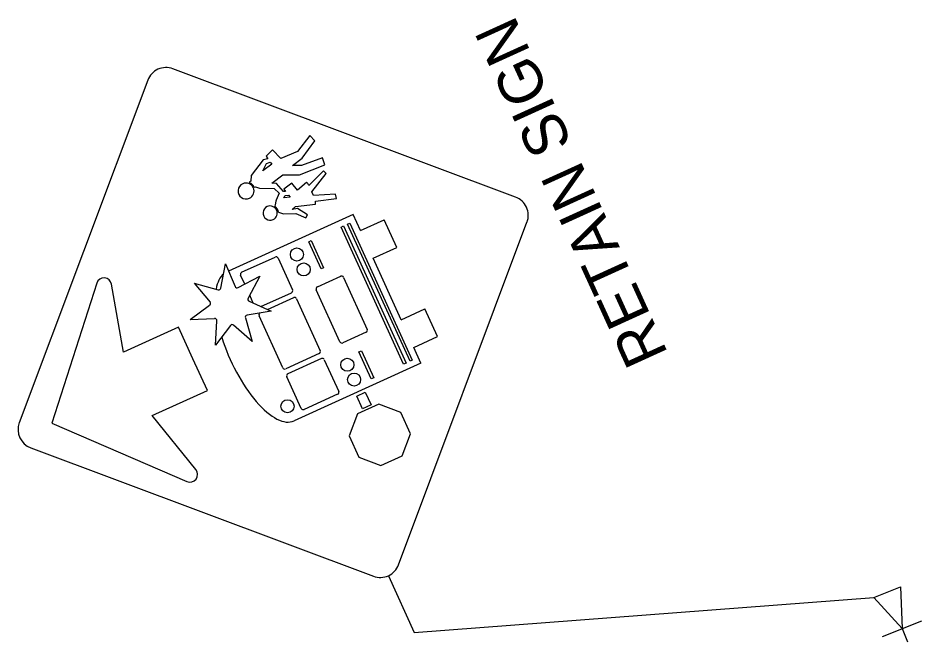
# Model space of a CAD drawing. Extents: x 2096999 to 2102576, y 682920 to 687015.
# Drawn here: x 2101971.4 to 2102115.9, y 683833.4 to 683933.2 of the extents above; entities that cross this region are included whole.
import ezdxf

# ---------------------------------------------------------------- set-up
doc = ezdxf.new("R2010")
doc.units = 0
doc.layers.add('Default', color=7, linetype='Continuous')

msp = doc.modelspace()

# ---------------------------------------------------------------- linework, layer by layer
at = {"layer": 'Default'}
for p, q in [((2102013.89, 683904.46), (2102013.89, 683904.46)), ((2102014.09, 683904.83), (2102014.09, 683904.83)), ((2102014.64, 683904.87), (2102014.64, 683904.87)), ((2102014.88, 683904.57), (2102014.88, 683904.57)), ((2102012.5, 683903.34), (2102012.5, 683903.34)), ((2102012.57, 683903.91), (2102012.57, 683903.91)), ((2102024.99, 683901.77), (2102005.05, 683892.7)), ((2102013.83, 683901.9), (2102013.83, 683901.9)), ((2102015.79, 683901.98), (2102015.79, 683901.98)), ((2102017.65, 683901.74), (2102017.65, 683901.74)), ((2102026.14, 683899.23), (2102024.99, 683901.77)), ((2102017.42, 683901.28), (2102017.42, 683901.28)), ((2102026.14, 683899.23), (2102029.94, 683900.96)), ((2102031.96, 683896.52), (2102029.94, 683900.96)), ((2102028.16, 683894.79), (2102031.96, 683896.52)), ((2102007.13, 683892.55), (2102012.5, 683894.99)), ((2102012.96, 683894.82), (2102015.27, 683889.74)), ((2102032.63, 683884.96), (2102028.16, 683894.79)), ((2102003.82, 683890.03), (2102004.56, 683893.9)), ((2102004.56, 683893.9), (2102006.08, 683890.26)), ((2102006.57, 683890.09), (2102010.05, 683891.92)), ((2102007.62, 683890.64), (2102006.96, 683892.09)), ((2102010.05, 683891.92), (2102008.15, 683888.39)), ((2101984.07, 683891.16), (2101984.07, 683891.16)), ((2101999.52, 683890.81), (2102002.07, 683887.76)), ((2101999.52, 683890.81), (2102003.39, 683889.76)), ((2102008.99, 683887.62), (2102008.42, 683888.88)), ((2102010.2, 683887.06), (2102015.09, 683889.28)), ((2102011.26, 683886.58), (2102015.45, 683888.49)), ((2101998.87, 683884.98), (2102002.01, 683887.26)), ((2102008.32, 683887.91), (2102011.86, 683886.31)), ((2102015.91, 683888.32), (2102019.7, 683879.99)), ((2102011.86, 683886.31), (2102008, 683885.68)), ((2102013.7, 683877.26), (2102009.92, 683885.59)), ((2102032.63, 683884.96), (2102036.43, 683886.69)), ((2102038.45, 683882.25), (2102036.43, 683886.69)), ((2101998.87, 683884.98), (2102002.8, 683885.16)), ((2102002.97, 683880.86), (2102003.17, 683884.8)), ((2102005.32, 683884.03), (2102002.97, 683880.86)), ((2102008.79, 683881.47), (2102005.83, 683884.08)), ((2102007.73, 683885.24), (2102008.79, 683881.47)), ((2102034.65, 683880.52), (2102038.45, 683882.25)), ((2102035.8, 683877.99), (2102034.65, 683880.52)), ((2102019.53, 683879.53), (2102014.17, 683877.09)), ((2102019.89, 683878.73), (2102014.53, 683876.3)), ((2102020.35, 683878.56), (2102022.66, 683873.49)), ((2102035.8, 683877.99), (2102015.51, 683868.76)), ((2102016.66, 683870.76), (2102014.35, 683875.83)), ((2102022.48, 683873.03), (2102017.12, 683870.59)), ((2102029.06, 683871.43), (2102025.64, 683869.88)), ((2102032.58, 683870.11), (2102029.06, 683871.43)), ((2102025.64, 683869.88), (2102024.33, 683866.36)), ((2102034.13, 683866.7), (2102032.58, 683870.11)), ((2102032.82, 683863.18), (2102034.13, 683866.7)), ((2102024.33, 683866.36), (2102025.88, 683862.94)), ((2102025.88, 683862.94), (2102029.4, 683861.63)), ((2102029.4, 683861.63), (2102032.82, 683863.18)), ((2102108.25, 683840.5), (2102112.5, 683842.19)), ((2102112.5, 683842.19), (2102112.81, 683835.54)), ((2102112.81, 683835.54), (2102108.25, 683840.5)), ((2102109.62, 683834.28), (2102115.95, 683836.79)), ((2102112.81, 683835.54), (2102113.66, 683833.39))]:
    msp.add_line(p, q, dxfattribs=at)
for points in [[(2102050.94, 683904.58), (2101996.14, 683925.12)], [(2101992.1, 683923.28), (2101971.56, 683868.48)], [(2102013.02, 683902.17), (2102013.83, 683901.9), (2102015.79, 683901.98), (2102017.42, 683901.28), (2102017.65, 683901.74), (2102016.05, 683902.76), (2102015.23, 683902.62), (2102015.72, 683903.09), (2102018.94, 683903.45), (2102018.92, 683903.92), (2102022.32, 683904.35), (2102022.14, 683905.05), (2102018.61, 683904.82), (2102018.35, 683905.43), (2102020.66, 683908.36), (2102020.24, 683908.79), (2102017.89, 683906.43), (2102017.83, 683906.54), (2102017.78, 683906.65), (2102017.69, 683906.78), (2102017.6, 683906.86), (2102017.51, 683906.91), (2102016.08, 683905.7), (2102015.16, 683906.8), (2102013.9, 683905.86), (2102014.15, 683905.5), (2102013.8, 683905.48), (2102012.68, 683906.73), (2102011.95, 683906.82), (2102013.72, 683908.13), (2102016.36, 683908.12), (2102020.42, 683909.75), (2102020.08, 683910.88), (2102016.69, 683909.62), (2102015.26, 683909.64), (2102016.81, 683910.81), (2102018.83, 683913.61), (2102018.02, 683914.44), (2102016.08, 683911.86), (2102013.37, 683910.78), (2102012.04, 683912.17), (2102011.06, 683911.13), (2102011.33, 683910.69), (2102010.56, 683910.56), (2102008.63, 683908.01), (2102008.61, 683907.14), (2102008.39, 683907), (2102008.4, 683906.88)], [(2102011.69, 683910.18), (2102011.96, 683909.84), (2102010.54, 683908.76), (2102011.13, 683909.97), (2102011.69, 683910.18)], [(2102009.15, 683906.16), (2102009.33, 683906.24), (2102009.98, 683905.99), (2102010.04, 683906), (2102012.32, 683905.93), (2102013.15, 683905.2), (2102012.63, 683904.09), (2102012.57, 683903.91), (2102012.5, 683903.34)], [(2102014.64, 683904.87), (2102014.88, 683904.57), (2102013.89, 683904.46), (2102014.09, 683904.83), (2102014.64, 683904.87)], [(2102012.5, 683903.34), (2102012.45, 683903.11)], [(2102032.24, 683845.75), (2102052.77, 683900.55)], [(2102019.24, 683890.21), (2102022.97, 683891.91)], [(2102023.43, 683891.73), (2102027.21, 683883.41)], [(2101983.95, 683890.81), (2101976.74, 683868.38), (2101998.38, 683859.08)], [(2101999.33, 683878.7), (2101997.02, 683883.77), (2101988.23, 683879.77), (2101986.32, 683890.65)], [(2102022.85, 683881.42), (2102019.07, 683889.75)], [(2102027.04, 683882.94), (2102023.31, 683881.25)], [(2101999.81, 683860.97), (2101992.83, 683869.62), (2102001.64, 683873.63), (2101999.33, 683878.7)], [(2101973.4, 683864.45), (2102028.2, 683843.91)], [(2102030.6, 683843.99), (2102034.73, 683834.91), (2102108.25, 683840.5)]]:
    msp.add_lwpolyline(points, dxfattribs=at)
for points in [[(2102033.04, 683877.84), (2102023.06, 683899.79), (2102023.44, 683899.96), (2102033.42, 683878.01)], [(2102034.06, 683878.3), (2102024.07, 683900.25), (2102024.45, 683900.42), (2102034.43, 683878.47)], [(2102019.86, 683893.11), (2102017.89, 683897.43), (2102018.27, 683897.61), (2102020.24, 683893.28)], [(2102027.87, 683875.49), (2102025.9, 683879.81), (2102026.28, 683879.99), (2102028.25, 683875.66)], [(2102026.9, 683873.35), (2102027.82, 683871.33), (2102026.47, 683870.72), (2102025.55, 683872.73)]]:
    msp.add_lwpolyline(points, close=True, dxfattribs=at)
for centre in [(2102015.97, 683895.39), (2102017.05, 683893.01), (2102024.03, 683877.75), (2102025.11, 683875.37), (2102014.47, 683871.11)]:
    msp.add_circle(centre, 1.05, dxfattribs=at)
for centre, radius, start, end in [((2101995.04, 683922.18), 3.14, 69.4559, 159.458), ((2102007.84, 683905.55), 1.28, 114.458, 294.458), ((2102007.84, 683905.55), 1.28, 294.458, 114.458), ((2102007.84, 683905.55), 1.44, 25.2657, 67.1381), ((2102049.84, 683901.65), 3.14, 339.4559, 69.458), ((2102011.69, 683902.02), 1.14, 114.458, 294.458), ((2102011.69, 683902.02), 1.14, 294.458, 114.458), ((2102011.69, 683902.02), 1.33, 6.57, 55.3516), ((2102012.64, 683894.67), 0.348, 24.458, 114.458), ((2101985.11, 683890.44), 1.22, 9.9853, 162.16), ((2102007.28, 683892.23), 0.348, 114.458, 204.458), ((2102023.11, 683891.59), 0.348, 24.458, 114.458), ((2102003.48, 683890.09), 0.348, 254.7728, 349.1199), ((2102006.4, 683890.4), 0.348, 202.6931, 297.6908), ((2102019.38, 683889.89), 0.348, 114.458, 204.458), ((2102008.46, 683888.23), 0.348, 151.6716, 245.6888), ((2102014.95, 683889.6), 0.348, 294.458, 24.458), ((2102015.6, 683888.17), 0.348, 24.458, 114.458), ((2102001.81, 683887.54), 0.348, 305.9926, 39.9359), ((2102008.06, 683885.33), 0.348, 99.3189, 195.734), ((2102010.23, 683885.73), 0.348, 138.9148, 204.458), ((2102002.82, 683884.82), 0.348, 357.0816, 92.756), ((2102005.6, 683883.82), 0.348, 48.5085, 143.3177), ((2102026.9, 683883.26), 0.348, 294.458, 24.458), ((2102023.17, 683881.57), 0.348, 204.458, 294.458), ((2102019.38, 683879.84), 0.348, 294.458, 24.458), ((2102020.03, 683878.42), 0.348, 24.458, 114.458), ((2102014.02, 683877.41), 0.348, 204.458, 294.458), ((2102014.67, 683875.98), 0.348, 114.458, 204.458), ((2102022.34, 683873.34), 0.348, 294.458, 24.458), ((2102016.98, 683870.91), 0.348, 204.458, 294.458), ((2101974.5, 683867.38), 3.14, 159.458, 249.458), ((2101998.86, 683860.2), 1.22, 246.7557, 38.9307), ((2102029.3, 683846.85), 3.14, 249.458, 339.458)]:
    msp.add_arc(centre, radius, start, end, dxfattribs=at)
for start_param, end_param in [(0.098799, 0.527026), (1.265977, 3.141593)]:
    msp.add_ellipse((2102010.1, 683880.65), major_axis=(-5.41, 11.89), ratio=0.399852, start_param=start_param, end_param=end_param, dxfattribs=at)

# ---------------------------------------------------------------- texts
msp.add_text('RETAIN SIGN', height=7, rotation=114.4888, dxfattribs=at).set_placement((2102075.41, 683879.49))

doc.saveas('drawing.dxf')
